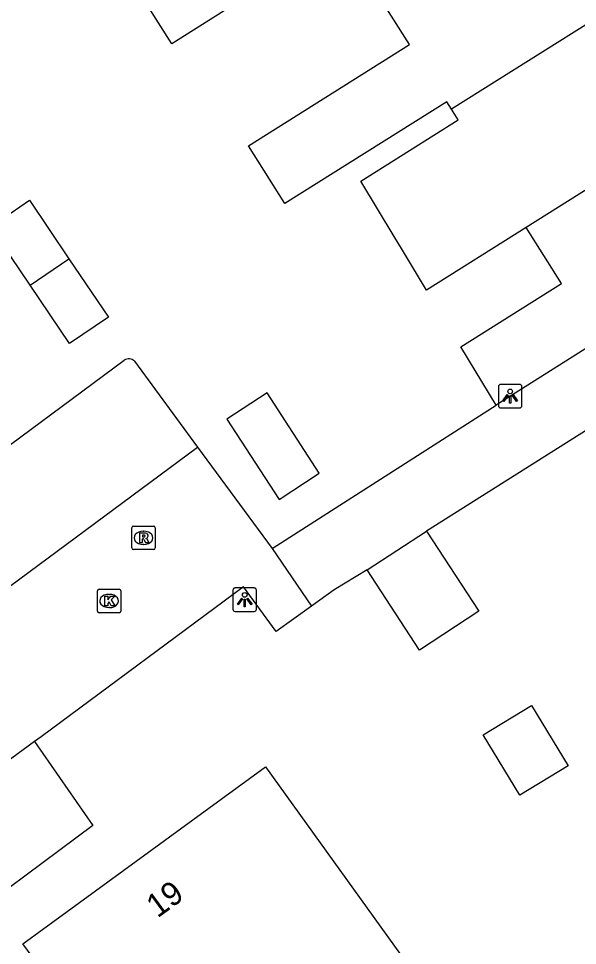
# Model space of a CAD drawing. Extents: x 161801 to 162379, y 382315 to 382832.
# Drawn here: x 162071.44 to 162095.18, y 382446.1 to 382485.49 of the extents above; entities that cross this region are included whole.
import ezdxf

# ---------------------------------------------------------------- set-up
doc = ezdxf.new("R2010")
doc.units = 0
for name, color, linetype in [('IMGEO_Kolk', 7, 'Continuous'), ('IMGEO_Lichtpunt', 7, 'Continuous'), ('IMGEO_Pand', 7, 'Continuous'), ('IMGEO_Pand_nummerreeks', 7, 'Continuous'), ('IMGEO_Parkeervlak_halfverhard', 7, 'Continuous'), ('IMGEO_Parkeervlak_open', 7, 'Continuous'), ('IMGEO_Rijbaan_lokaal_open', 7, 'Continuous'), ('IMGEO_Rioolput', 7, 'Continuous'), ('IMGEO_Voetpad_open', 7, 'Continuous')]:
    doc.layers.add(name, color=color, linetype=linetype)

msp = doc.modelspace()

# ---------------------------------------------------------------- linework, layer by layer
at = {"layer": 'IMGEO_Kolk'}
for p, q in [((162074.787, 382460.317), (162074.787, 382461.169)), ((162074.862, 382461.243), (162075.714, 382461.243)), ((162075.788, 382461.169), (162075.788, 382460.317)), ((162075.275, 382461.023), (162075.3, 382461.023)), ((162075.298, 382460.463), (162075.273, 382460.463)), ((162075.714, 382460.243), (162074.862, 382460.243))]:
    msp.add_line(p, q, dxfattribs=at)
for points in [[(162074.787, 382460.317), (162074.787, 382461.169)], [(162074.862, 382461.243), (162075.714, 382461.243)], [(162075.788, 382461.169), (162075.788, 382460.317)], [(162075.108, 382460.943), (162075.231, 382460.943), (162075.231, 382460.792), (162075.361, 382460.943), (162075.525, 382460.943), (162075.379, 382460.792), (162075.532, 382460.543), (162075.38, 382460.543), (162075.295, 382460.707), (162075.231, 382460.64), (162075.231, 382460.543), (162075.108, 382460.543), (162075.108, 382460.943)], [(162075.714, 382460.243), (162074.862, 382460.243)]]:
    msp.add_lwpolyline(points, dxfattribs=at)
for centre, start, end in [((162074.864, 382461.167), 91.552, 178.448), ((162074.864, 382461.167), 91.552, 178.448), ((162075.712, 382461.167), 1.552, 88.448), ((162075.712, 382461.167), 1.552, 88.448), ((162074.864, 382460.319), 181.552, 268.448), ((162074.864, 382460.319), 181.552, 268.448), ((162075.712, 382460.319), 271.552, 358.448), ((162075.712, 382460.319), 271.552, 358.448)]:
    msp.add_arc(centre, 0.0765, start, end, dxfattribs=at)
for centre, major_axis, ratio, start_param, end_param in [((162075.274, 382460.743), (-0.387, 0.002), 0.722429, 4.712389, 7.853982), ((162075.299, 382460.743), (-0.39, 0.002), 0.717154, 1.570796, 4.712389)]:
    msp.add_ellipse(centre, major_axis=major_axis, ratio=ratio, start_param=start_param, end_param=end_param, dxfattribs=at)
at = {"layer": 'IMGEO_Lichtpunt'}
for p, q in [((162091.827, 382469.851), (162091.827, 382469.044)), ((162091.827, 382469.851), (162091.827, 382469.044)), ((162092.729, 382469.946), (162091.921, 382469.946)), ((162092.729, 382469.946), (162091.921, 382469.946)), ((162092.823, 382469.044), (162092.823, 382469.851)), ((162092.823, 382469.044), (162092.823, 382469.851)), ((162091.921, 382468.95), (162092.729, 382468.95)), ((162091.921, 382468.95), (162092.729, 382468.95)), ((162080.548, 382461.2), (162080.548, 382460.393)), ((162080.548, 382461.2), (162080.548, 382460.393)), ((162081.45, 382461.295), (162080.642, 382461.295)), ((162081.45, 382461.295), (162080.642, 382461.295)), ((162081.544, 382460.393), (162081.544, 382461.2)), ((162081.544, 382460.393), (162081.544, 382461.2)), ((162080.642, 382460.299), (162081.45, 382460.299)), ((162080.642, 382460.299), (162081.45, 382460.299))]:
    msp.add_line(p, q, dxfattribs=at)
for points in [[(162092.201, 382469.515), (162092.24, 382469.487), (162092.052, 382469.225), (162092.014, 382469.252), (162092.201, 382469.515)], [(162092.303, 382469.467), (162092.35, 382469.467), (162092.35, 382469.145), (162092.303, 382469.145), (162092.303, 382469.467)], [(162092.413, 382469.487), (162092.451, 382469.514), (162092.638, 382469.252), (162092.599, 382469.224), (162092.413, 382469.487)], [(162080.922, 382460.864), (162080.961, 382460.836), (162080.773, 382460.574), (162080.735, 382460.601), (162080.922, 382460.864)], [(162081.024, 382460.816), (162081.071, 382460.816), (162081.071, 382460.494), (162081.024, 382460.494), (162081.024, 382460.816)], [(162081.134, 382460.836), (162081.172, 382460.863), (162081.359, 382460.601), (162081.32, 382460.573), (162081.134, 382460.836)]]:
    msp.add_lwpolyline(points, dxfattribs=at)
for centre in [(162092.326, 382469.649), (162081.047, 382460.998)]:
    msp.add_circle(centre, 0.0994, dxfattribs=at)
for centre, start, end in [((162091.921, 382469.851), 90, 180), ((162091.921, 382469.851), 90, 180), ((162092.729, 382469.851), 0, 90), ((162092.729, 382469.851), 0, 90), ((162091.921, 382469.044), 180, 270), ((162091.921, 382469.044), 180, 270), ((162092.729, 382469.044), 270, 0), ((162092.729, 382469.044), 270, 360), ((162080.642, 382461.2), 90, 180), ((162080.642, 382461.2), 90, 180), ((162081.45, 382461.2), 0, 90), ((162081.45, 382461.2), 0, 90), ((162080.642, 382460.393), 180, 270), ((162080.642, 382460.393), 180, 270), ((162081.45, 382460.393), 270, 0), ((162081.45, 382460.393), 270, 360)]:
    msp.add_arc(centre, 0.0946, start, end, dxfattribs=at)
at = {"layer": 'IMGEO_Pand'}
for points in [[(162079.217, 382488.544), (162080.717, 382486.156), (162077.952, 382484.419), (162076.454, 382486.804), (162077.644, 382487.553)], [(162089.834, 382481.646), (162089.638, 382481.958), (162082.746, 382477.63), (162081.204, 382480.086), (162088.05, 382484.385), (162086.624, 382486.655)], [(162097.591, 382486.531), (162089.834, 382481.646)], [(162093.01, 382476.61), (162088.778, 382473.945), (162087.919, 382475.365), (162087.75, 382475.644), (162087.398, 382476.226), (162085.975, 382478.581), (162090.123, 382481.185), (162089.834, 382481.646)], [(162100.752, 382481.485), (162093.01, 382476.61)], [(162071.927, 382474.165), (162070.244, 382476.649), (162071.9, 382477.77), (162073.582, 382475.286)], [(162091.73, 382469.061), (162090.229, 382471.544), (162094.501, 382474.235), (162093.01, 382476.61)], [(162103.771, 382476.665), (162091.73, 382469.061)], [(162073.582, 382475.286), (162075.261, 382472.807), (162073.609, 382471.681), (162071.927, 382474.165)], [(162071.927, 382474.165), (162073.582, 382475.286)], [(162081.996, 382469.587), (162080.284, 382468.475), (162082.505, 382465.058), (162084.217, 382466.17), (162081.996, 382469.587)], [(162088.772, 382463.713), (162090.993, 382460.304), (162088.469, 382458.657), (162086.247, 382462.066)], [(162086.247, 382462.066), (162088.772, 382463.713)], [(162091.177, 382455.062), (162093.228, 382456.305), (162094.788, 382453.733), (162092.738, 382452.489), (162091.177, 382455.062)], [(162071.617, 382446.168), (162081.935, 382453.69), (162087.988, 382445.269), (162082.525, 382441.34), (162090.145, 382430.746), (162087.7, 382428.445), (162084.155, 382425.896), (162078.92, 382433.174), (162080.398, 382434.237), (162071.617, 382446.168)]]:
    msp.add_lwpolyline(points, dxfattribs=at)
at = {"layer": 'IMGEO_Parkeervlak_halfverhard'}
msp.add_lwpolyline([(162072.121, 382454.773), (162074.6, 382451.197), (162068.196, 382446.446), (162067.074, 382448.077)], dxfattribs=at)
at = {"layer": 'IMGEO_Parkeervlak_open'}
for points in [[(162063.569, 382461.806), (162075.931, 382470.972)], [(162076.36, 382470.928), (162079.043, 382467.284)]]:
    msp.add_lwpolyline(points, dxfattribs=at)
msp.add_arc((162076.122, 382470.719), 0.317, 41.2844, 127.0035, dxfattribs=at)
at = {"layer": 'IMGEO_Rijbaan_lokaal_open'}
for points in [[(162065.906, 382457.553), (162079.043, 382467.284)], [(162079.043, 382467.284), (162082.212, 382462.98)], [(162082.212, 382462.98), (162083.88, 382460.516)], [(162083.88, 382460.516), (162082.387, 382459.443), (162080.992, 382461.339), (162072.399, 382454.977), (162072.121, 382454.773)], [(162072.121, 382454.773), (162065.693, 382450.051), (162066.998, 382448.171)]]:
    msp.add_lwpolyline(points, dxfattribs=at)
at = {"layer": 'IMGEO_Rioolput'}
for p, q in [((162076.248, 382463.001), (162076.248, 382463.853)), ((162076.323, 382463.927), (162077.175, 382463.927)), ((162077.249, 382463.853), (162077.249, 382463.001)), ((162076.736, 382463.707), (162076.761, 382463.707)), ((162076.759, 382463.147), (162076.734, 382463.147)), ((162077.175, 382462.927), (162076.323, 382462.927))]:
    msp.add_line(p, q, dxfattribs=at)
for points in [[(162076.248, 382463.001), (162076.248, 382463.853)], [(162076.323, 382463.927), (162077.175, 382463.927)], [(162077.249, 382463.853), (162077.249, 382463.001)], [(162076.837, 382463.625), (162076.585, 382463.627), (162076.585, 382463.227)], [(162076.763, 382463.546), (162076.709, 382463.546), (162076.709, 382463.465)], [(162076.709, 382463.465), (162076.761, 382463.465)], [(162076.585, 382463.227), (162076.709, 382463.227), (162076.709, 382463.389), (162076.72, 382463.389)], [(162076.767, 382463.36), (162076.838, 382463.227), (162076.978, 382463.227), (162076.913, 382463.353)], [(162077.175, 382462.927), (162076.323, 382462.927)]]:
    msp.add_lwpolyline(points, dxfattribs=at)
for centre, radius, start, end in [((162076.325, 382463.851), 0.0765, 91.552, 178.448), ((162076.325, 382463.851), 0.0765, 91.552, 178.448), ((162077.173, 382463.851), 0.0765, 1.552, 88.448), ((162077.173, 382463.851), 0.0765, 1.552, 88.448), ((162076.745, 382463.654), 0.19, 274.7715, 282.9687), ((162076.769, 382463.45), 0.0964, 77.0061, 93.1865), ((162076.783, 382463.507), 0.0378, 276.6634, 79.6772), ((162076.836, 382463.515), 0.109, 350.3612, 89.416), ((162076.834, 382463.515), 0.112, 277.5842, 350.9817), ((162076.818, 382463.3), 0.108, 29.5134, 73.7905), ((162076.719, 382463.336), 0.0533, 26.0293, 88.6989), ((162076.325, 382463.003), 0.0765, 181.552, 268.448), ((162076.325, 382463.003), 0.0765, 181.552, 268.448), ((162077.173, 382463.003), 0.0765, 271.552, 358.448), ((162077.173, 382463.003), 0.0765, 271.552, 358.448)]:
    msp.add_arc(centre, radius, start, end, dxfattribs=at)
for centre, major_axis, ratio, start_param, end_param in [((162076.735, 382463.427), (-0.387, 0.002), 0.722429, 4.712389, 7.853982), ((162076.76, 382463.427), (-0.39, 0.002), 0.717154, 1.570796, 4.712389)]:
    msp.add_ellipse(centre, major_axis=major_axis, ratio=ratio, start_param=start_param, end_param=end_param, dxfattribs=at)
at = {"layer": 'IMGEO_Voetpad_open'}
for points in [[(162097.905, 382469.475), (162088.772, 382463.713)], [(162082.212, 382462.98), (162083.316, 382463.686), (162091.73, 382469.061)], [(162086.247, 382462.066), (162084.852, 382461.215), (162083.88, 382460.516)]]:
    msp.add_lwpolyline(points, dxfattribs=at)

# ---------------------------------------------------------------- texts
at = {"layer": 'IMGEO_Pand_nummerreeks'}
msp.add_text('19', height=1, rotation=36.0906, dxfattribs=at).set_placement((162077.34, 382447.246))

doc.saveas('drawing.dxf')
